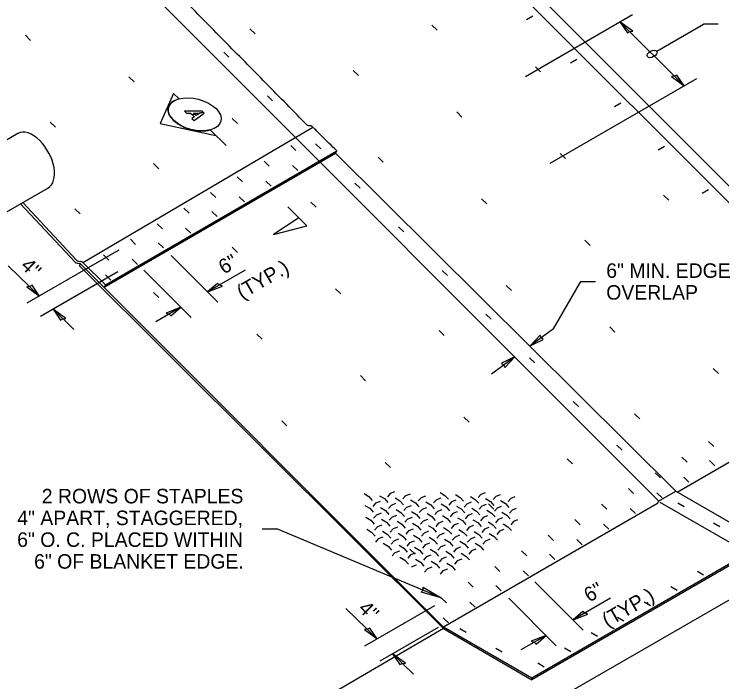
# Model space of a CAD drawing. Extents: x 99862 to 103151, y 100000 to 102076.
# Drawn here: x 101630 to 102411, y 100758 to 101495 of the extents above; entities that cross this region are included whole.
import ezdxf

# ---------------------------------------------------------------- set-up
doc = ezdxf.new("R2010")
doc.units = 0
for name, color, linetype in [('Level 1', 7, 'Continuous'), ('Level 11', 7, 'Continuous'), ('Level 15', 7, 'Continuous'), ('Level 20', 7, 'Continuous'), ('Level 3', 7, 'Continuous'), ('Level 36', 7, 'Continuous'), ('Level 4', 7, 'Continuous'), ('Level 5', 7, 'Continuous'), ('Level 7', 7, 'Continuous')]:
    doc.layers.add(name, color=color, linetype=linetype)

msp = doc.modelspace()

# ---------------------------------------------------------------- linework, layer by layer
at = {"layer": 'Level 1'}
for p, q in [((102612.56, 101110.84), (101833.9, 101890.08)), ((102742.49, 101035.83), (101698.37, 100433.01)), ((102103.79, 100817.24), (101571.09, 100506.49))]:
    msp.add_line(p, q, dxfattribs=at)
at = {"layer": 'Level 11'}
for points in [[(102016.17, 100965.97), (102021.52, 100962.7), (102025.25, 100958.36)], [(102033.32, 100963.67), (102038.66, 100960.4), (102042.39, 100956.07)], [(102049.88, 100967.79), (102044.98, 100965.91), (102041.87, 100962.52)], [(102066.87, 100965.49), (102062, 100963.62), (102058.92, 100960.22)], [(102083.8, 100963.2), (102078.95, 100961.33), (102075.91, 100957.94)], [(102100.05, 100967.3), (102105.33, 100964.06), (102109.06, 100959.78)], [(102116.82, 100965.02), (102122.09, 100961.79), (102125.82, 100957.52)], [(102133.52, 100962.74), (102138.78, 100959.52), (102142.51, 100955.26)], [(102149.49, 100966.81), (102144.78, 100964.96), (102141.85, 100961.61)], [(102166.04, 100964.55), (102161.36, 100962.7), (102158.46, 100959.35)], [(102182.52, 100962.29), (102177.87, 100960.45), (102175, 100957.1)], [(102033.82, 100957.21), (102028.88, 100955.32), (102025.73, 100951.89)], [(102050.93, 100954.93), (102046.02, 100953.03), (102042.9, 100949.6)], [(102050.41, 100961.37), (102055.73, 100958.11), (102059.46, 100953.78)], [(102067.42, 100959.08), (102072.74, 100955.82), (102076.47, 100951.51)], [(102084.37, 100956.8), (102089.68, 100953.55), (102093.41, 100949.24)], [(102100.65, 100960.92), (102095.84, 100959.05), (102092.82, 100955.66)], [(102101.26, 100954.53), (102106.55, 100951.28), (102110.29, 100946.98)], [(102117.45, 100958.65), (102112.66, 100956.78), (102109.67, 100953.39)], [(102134.17, 100956.39), (102129.42, 100954.51), (102126.46, 100951.13)], [(102150.84, 100954.13), (102146.11, 100952.26), (102143.18, 100948.88)], [(102150.16, 100960.48), (102155.41, 100957.27), (102159.14, 100953.01)], [(102166.74, 100958.23), (102171.98, 100955.02), (102175.71, 100950.77)], [(102017.12, 100953.03), (102022.49, 100949.75), (102026.22, 100945.39)], [(102034.33, 100950.74), (102039.68, 100947.46), (102043.42, 100943.11)], [(102051.46, 100948.46), (102056.8, 100945.19), (102060.55, 100940.85)], [(102067.98, 100952.64), (102063.09, 100950.75), (102060, 100947.32)], [(102068.53, 100946.19), (102073.86, 100942.92), (102077.61, 100938.59)], [(102084.95, 100950.37), (102080.09, 100948.48), (102077.04, 100945.06)], [(102101.86, 100948.11), (102097.03, 100946.21), (102094.01, 100942.8)], [(102118.07, 100952.26), (102123.36, 100949.03), (102127.1, 100944.73)], [(102134.83, 100950.01), (102140.1, 100946.78), (102143.84, 100942.49)], [(102151.51, 100947.76), (102156.78, 100944.54), (102160.52, 100940.26)], [(102167.43, 100951.89), (102162.74, 100950.02), (102159.83, 100946.64)], [(102183.97, 100949.65), (102179.3, 100947.78), (102176.42, 100944.41)], [(102018.08, 100940.01), (102023.46, 100936.71), (102027.21, 100932.33)], [(102034.83, 100944.25), (102029.87, 100942.33), (102026.72, 100938.87)], [(102051.99, 100941.98), (102047.06, 100940.06), (102043.94, 100936.6)], [(102069.08, 100939.72), (102064.18, 100937.8), (102061.09, 100934.35)], [(102085.53, 100943.93), (102090.85, 100940.67), (102094.6, 100936.34)], [(102102.46, 100941.67), (102107.78, 100938.42), (102111.53, 100934.1)], [(102118.7, 100945.86), (102113.91, 100943.96), (102110.91, 100940.55)], [(102119.33, 100939.43), (102124.64, 100936.18), (102128.39, 100931.87)], [(102135.48, 100943.61), (102130.71, 100941.72), (102127.74, 100938.31)], [(102152.19, 100941.37), (102147.45, 100939.48), (102144.51, 100936.08)], [(102168.84, 100939.15), (102164.13, 100937.25), (102161.22, 100933.85)], [(102168.14, 100945.53), (102173.39, 100942.31), (102177.14, 100938.04)], [(102035.84, 100931.2), (102030.86, 100929.26), (102027.7, 100925.77)], [(102035.33, 100937.74), (102040.7, 100934.45), (102044.46, 100930.07)], [(102052.52, 100935.47), (102057.88, 100932.19), (102061.64, 100927.83)], [(102069.64, 100933.22), (102074.99, 100929.94), (102078.75, 100925.59)], [(102086.11, 100937.46), (102081.24, 100935.54), (102078.18, 100932.1)], [(102086.7, 100930.98), (102092.04, 100927.71), (102095.79, 100923.35)], [(102103.07, 100935.22), (102098.23, 100933.3), (102095.2, 100929.86)], [(102119.97, 100932.98), (102115.16, 100931.07), (102112.15, 100927.63)], [(102136.79, 100930.75), (102132.01, 100928.84), (102129.04, 100925.4)], [(102136.14, 100937.19), (102141.43, 100933.95), (102145.18, 100929.64)], [(102152.87, 100934.96), (102158.16, 100931.73), (102161.91, 100927.43)], [(102169.55, 100932.75), (102174.82, 100929.52), (102178.58, 100925.22)], [(102185.42, 100936.93), (102180.74, 100935.04), (102177.86, 100931.64)], [(102019.04, 100926.9), (102024.44, 100923.59), (102028.2, 100919.19)], [(102036.35, 100924.65), (102041.74, 100921.34), (102045.5, 100916.95)], [(102053.06, 100928.95), (102048.11, 100927.01), (102044.98, 100923.52)], [(102070.2, 100926.7), (102065.29, 100924.76), (102062.19, 100921.28)], [(102087.28, 100924.47), (102082.4, 100922.53), (102079.32, 100919.05)], [(102103.68, 100928.74), (102109.01, 100925.48), (102112.77, 100921.13)], [(102120.6, 100926.51), (102125.92, 100923.26), (102129.69, 100918.92)], [(102137.45, 100924.3), (102142.77, 100921.04), (102146.53, 100916.71)], [(102153.56, 100928.54), (102148.81, 100926.62), (102145.86, 100923.19)], [(102170.25, 100926.33), (102165.53, 100924.41), (102162.61, 100920.98)], [(102036.86, 100918.07), (102031.87, 100916.1), (102028.7, 100912.59)], [(102054.13, 100915.83), (102049.17, 100913.87), (102046.03, 100910.36)], [(102053.59, 100922.4), (102058.97, 100919.11), (102062.73, 100914.72)], [(102070.76, 100920.17), (102076.13, 100916.88), (102079.9, 100912.5)], [(102087.87, 100917.94), (102093.22, 100914.66), (102097, 100910.29)], [(102104.29, 100922.24), (102099.44, 100920.3), (102096.4, 100916.83)], [(102104.91, 100915.72), (102110.25, 100912.45), (102114.03, 100908.08)], [(102121.24, 100920.02), (102116.41, 100918.09), (102113.4, 100914.62)], [(102138.12, 100917.82), (102133.32, 100915.88), (102130.34, 100912.41)], [(102154.93, 100915.62), (102150.17, 100913.68), (102147.21, 100910.22)], [(102154.24, 100922.09), (102159.54, 100918.84), (102163.31, 100914.52)], [(102037.37, 100911.47), (102042.77, 100908.16), (102046.55, 100903.74)], [(102054.66, 100909.25), (102060.06, 100905.94), (102063.84, 100901.53)], [(102071.33, 100913.61), (102066.4, 100911.65), (102063.29, 100908.14)], [(102071.89, 100907.03), (102077.27, 100903.73), (102081.06, 100899.33)], [(102088.46, 100911.39), (102083.56, 100909.43), (102080.48, 100905.93)], [(102105.52, 100909.19), (102100.65, 100907.22), (102097.6, 100903.72)], [(102121.88, 100913.52), (102127.21, 100910.25), (102130.99, 100905.89)], [(102138.78, 100911.32), (102144.11, 100908.05), (102147.89, 100903.7)], [(102055.2, 100902.64), (102050.23, 100900.65), (102047.15, 100897.19)], [(102072.46, 100900.43), (102067.51, 100898.44), (102064.39, 100894.91)], [(102089.05, 100904.82), (102094.42, 100901.53), (102098.21, 100897.14)], [(102106.14, 100902.63), (102111.5, 100899.34), (102115.29, 100894.95)], [(102122.52, 100906.99), (102117.68, 100905.03), (102114.66, 100901.53)], [(102123.16, 100900.44), (102128.52, 100897.16), (102132.3, 100892.78)], [(102139.45, 100904.8), (102134.64, 100902.84), (102131.65, 100899.34)], [(102055.75, 100896.01), (102061.16, 100892.69), (102064.95, 100888.26)], [(102073.03, 100893.81), (102078.43, 100890.5), (102082.22, 100886.08)], [(102089.64, 100898.23), (102084.73, 100896.25), (102081.64, 100892.71)], [(102090.24, 100891.62), (102095.63, 100888.32), (102099.43, 100883.9)], [(102106.76, 100896.04), (102101.87, 100894.06), (102098.82, 100890.53)], [(102123.81, 100893.86), (102118.95, 100891.88), (102115.92, 100888.36)], [(102073.6, 100887.17), (102068.64, 100885.16), (102068.32, 100884.8)], [(102090.83, 100884.99), (102085.9, 100882.98), (102082.81, 100879.42)], [(102107.38, 100889.44), (102112.76, 100886.14), (102116.56, 100881.74)], [(102108, 100882.82), (102103.1, 100880.81), (102100.04, 100877.25)]]:
    msp.add_lwpolyline(points, dxfattribs=at)
at = {"layer": 'Level 15'}
for p, q in [((102194.01, 101425.83), (102312.15, 101494.04)), ((102298.3, 101486.04), (102369.08, 101415.47)), ((102338.89, 101453.75), (102390.36, 101483.47)), ((102406.36, 101483.47), (102390.36, 101483.47)), ((102221.35, 101330.17), (102382.94, 101423.47)), ((101745.82, 101234.34), (101644.47, 101175.82)), ((101803.54, 101228.57), (101855.02, 101177.06)), ((101623.91, 101217.28), (101658.32, 101183.82)), ((101773.23, 101212.39), (101825.54, 101160.04)), ((101884.98, 101212.21), (101843.71, 101188.38)), ((101744.65, 101210.44), (101659.45, 101161.25)), ((102225.11, 101147.79), (102255.16, 101199.84)), ((102255.16, 101199.84), (102271.16, 101199.84)), ((101673.3, 101169.25), (101696.24, 101146.94)), ((101814.23, 101171.36), (101786.52, 101155.36)), ((102225.11, 101147.79), (102199.26, 101128.94)), ((102182.33, 101116.59), (102156.47, 101097.74)), ((101903.92, 100927.21), (101919.92, 100927.21)), ((102101.29, 100851.14), (101919.92, 100927.21)), ((102204.42, 100868.85), (102257.83, 100815.41)), ((102175.79, 100850.59), (102228.1, 100798.24)), ((102287.79, 100850.55), (102246.52, 100826.72)), ((101996.16, 100839.29), (102030.57, 100805.83)), ((102093.76, 100842.31), (102016.72, 100797.83)), ((102097.77, 100818.33), (102033.69, 100781.33)), ((102216.79, 100809.56), (102189.08, 100793.56)), ((102047.54, 100789.33), (102070.48, 100767.02))]:
    msp.add_line(p, q, dxfattribs=at)
for points in [[(102298.3, 101486.04), (102306.46, 101474.13), (102308.92, 101475.45), (102312.41, 101475.74)], [(102369.08, 101415.47), (102360.92, 101427.37), (102358.46, 101426.06), (102354.97, 101425.77)], [(101658.32, 101183.82), (101650.16, 101195.72), (101647.7, 101194.41), (101644.21, 101194.12)], [(101843.71, 101188.38), (101860, 101194.7), (101856.7, 101195.88), (101854.66, 101197.79)], [(101673.3, 101169.25), (101681.46, 101157.34), (101683.93, 101158.66), (101687.42, 101158.94)], [(101814.23, 101171.36), (101797.94, 101165.04), (101801.24, 101163.86), (101803.28, 101161.95)], [(102199.26, 101128.94), (102213.78, 101135.71), (102211.37, 101137.77), (102210.14, 101140.69)], [(102182.33, 101116.59), (102167.8, 101109.82), (102170.21, 101107.76), (102171.44, 101104.84)], [(102101.29, 100851.14), (102079.08, 100857.22), (102081.21, 100859.56), (102081.39, 100862.72)], [(102246.52, 100826.72), (102262.81, 100833.05), (102259.51, 100834.22), (102257.47, 100836.13)], [(102030.57, 100805.83), (102022.41, 100817.74), (102019.95, 100816.42), (102016.46, 100816.13)], [(102216.79, 100809.56), (102200.5, 100803.24), (102203.8, 100802.06), (102205.84, 100800.15)], [(102047.54, 100789.33), (102055.7, 100777.42), (102058.17, 100778.74), (102061.66, 100779.02)]]:
    msp.add_lwpolyline(points, close=True, dxfattribs=at)
msp.add_ellipse((102333.69, 101450.75), major_axis=(-5.2, -3), ratio=0.57735, dxfattribs=at)
at = {"layer": 'Level 20'}
for p, q in [((101806.09, 101407.27), (101791.22, 101374.02)), ((101806.09, 101407.27), (101791.22, 101374.02)), ((101812.18, 101401.22), (101806.09, 101407.27)), ((101812.18, 101401.22), (101806.09, 101407.27)), ((101829.66, 101384.17), (101826.99, 101383.46)), ((101826.99, 101383.46), (101829.66, 101384.17)), ((101834.97, 101385.59), (101835, 101385.6)), ((101838.85, 101386.63), (101835, 101385.6)), ((101835, 101385.6), (101838.85, 101386.63)), ((101791.22, 101374.02), (101852.74, 101360.96)), ((101791.22, 101374.02), (101852.74, 101360.96)), ((101846.65, 101367.01), (101863.96, 101349.82)), ((101852.74, 101360.96), (101846.65, 101367.01)), ((101852.74, 101360.96), (101846.65, 101367.01)), ((101932.03, 101282.24), (101953.11, 101261.31))]:
    msp.add_line(p, q, dxfattribs=at)
for points in [[(101829.08, 101381.38), (101826.44, 101379.52), (101828.72, 101377.26), (101839.9, 101385.59), (101837.8, 101387.68), (101818.1, 101387.8), (101820.4, 101385.51), (101824.9, 101385.54), (101829.08, 101381.38)], [(101838.85, 101386.63), (101837.8, 101387.68), (101818.1, 101387.8), (101820.4, 101385.51), (101824.9, 101385.54), (101826.99, 101383.46)], [(101826.99, 101383.46), (101829.08, 101381.38), (101826.44, 101379.52), (101828.72, 101377.26), (101839.9, 101385.59), (101838.85, 101386.63)], [(101835, 101385.59), (101831.05, 101382.79), (101828.27, 101385.55), (101835, 101385.59)], [(101829.66, 101384.17), (101828.27, 101385.55), (101834.97, 101385.59)], [(101835, 101385.59), (101831.05, 101382.79), (101829.66, 101384.17)], [(101835, 101385.6), (101835, 101385.59)], [(101944.19, 101270.16), (101916.16, 101251.54), (101953.11, 101261.31), (101944.19, 101270.16)]]:
    msp.add_lwpolyline(points, dxfattribs=at)
msp.add_ellipse((101829.41, 101384.11), major_axis=(28.93, -7.57), ratio=0.572616, dxfattribs=at)
for start_param, end_param in [(2.349236, 5.49092), (2.349236, 3.025373), (3.025373, 3.920085), (3.920085, 5.49092)]:
    msp.add_ellipse((101829.41, 101384.11), major_axis=(28.93, -7.57), ratio=0.572616, start_param=start_param, end_param=end_param, dxfattribs=at)
at = {"layer": 'Level 3'}
for p, q in [((101634.49, 101362.93), (101379.93, 101215.96)), ((101413.08, 101155.93), (101667.64, 101302.9)), ((101413.08, 101155.93), (101667.64, 101302.9))]:
    msp.add_line(p, q, dxfattribs=at)
for centre, major_axis, start_param, end_param in [((101650.74, 101334.78), (-16.25, 28.15), 5.148721, 6.283185), ((101650.14, 101333.21), (-17.5, 30.31), 3.141593, 5.148721)]:
    msp.add_ellipse(centre, major_axis=major_axis, ratio=0.57735, start_param=start_param, end_param=end_param, dxfattribs=at)
at = {"layer": 'Level 36'}
for p, q in [((102202.37, 101492.39), (102195.36, 101488.37)), ((101890.22, 101478.43), (101896.01, 101472.8)), ((102090.94, 101482.46), (102096.73, 101476.83)), ((101642.72, 101471.26), (101648.51, 101465.63)), ((101861.44, 101452.63), (101867.22, 101447)), ((102250.74, 101444.49), (102243.73, 101440.47)), ((102004.25, 101432.62), (102010.04, 101426.99)), ((102204.97, 101436.64), (102210.76, 101431.02)), ((101756.75, 101425.44), (101762.54, 101419.81)), ((101909.59, 101404.5), (101915.37, 101398.87)), ((102299.11, 101396.58), (102292.11, 101392.57)), ((102118.28, 101386.8), (102124.07, 101381.17)), ((101670.06, 101375.6), (101675.84, 101369.97)), ((101870.78, 101379.63), (101876.57, 101374)), ((101935.3, 101349.71), (101941.09, 101344.08)), ((101962.72, 101351.75), (101968.51, 101346.12)), ((102347.48, 101348.68), (102340.48, 101344.66)), ((102031.59, 101336.96), (102037.38, 101331.33)), ((102232.31, 101340.99), (102238.1, 101335.36)), ((101784.09, 101329.79), (101789.87, 101324.16)), ((101905.84, 101332.49), (101911.63, 101326.86)), ((101937.33, 101327.66), (101943.11, 101322.03)), ((101876.37, 101315.26), (101882.16, 101309.63)), ((101907.86, 101310.44), (101913.65, 101304.81)), ((102005.89, 101308.26), (102011.68, 101302.63)), ((101846.9, 101298.04), (101852.69, 101292.41)), ((102395.85, 101300.78), (102388.85, 101296.76)), ((101878.39, 101293.21), (101884.18, 101287.58)), ((102145.62, 101291.14), (102151.41, 101285.51)), ((102346.34, 101295.17), (102352.13, 101289.54)), ((101957.4, 101287.41), (101963.19, 101281.78)), ((101697.39, 101279.94), (101703.18, 101274.31)), ((101817.44, 101280.81), (101823.22, 101275.18)), ((101848.29, 101277.04), (101854.08, 101271.41)), ((101787.97, 101263.58), (101793.76, 101257.95)), ((101819.46, 101258.76), (101825.25, 101253.13)), ((102054.04, 101260.13), (102059.83, 101254.5)), ((101758.5, 101246.35), (101764.29, 101240.72)), ((101789.15, 101242.57), (101794.94, 101236.94)), ((102259.65, 101245.33), (102265.44, 101239.7)), ((101870.71, 101237.56), (101876.49, 101231.93)), ((101729.04, 101229.13), (101734.82, 101223.5)), ((101760.52, 101224.3), (101766.31, 101218.67)), ((102102.19, 101212.01), (102107.98, 101206.38)), ((101731.06, 101207.08), (101736.85, 101201.45)), ((101984.74, 101191.75), (101990.52, 101186.12)), ((102172.95, 101195.48), (102178.74, 101189.85)), ((101784.01, 101187.72), (101789.8, 101182.09)), ((102150.34, 101163.88), (102156.13, 101158.25)), ((102286.99, 101149.67), (102292.77, 101144.04)), ((101898.04, 101141.9), (101903.83, 101136.27)), ((102098.77, 101145.93), (102104.56, 101140.3)), ((102198.49, 101115.76), (102204.28, 101110.13)), ((102401.02, 101103.85), (102406.8, 101098.22)), ((102012.07, 101096.09), (102017.86, 101090.46)), ((102246.64, 101067.64), (102252.43, 101062.01)), ((102126.1, 101050.27), (102131.89, 101044.64)), ((102314.32, 101054.01), (102320.11, 101048.38)), ((101925.38, 101046.24), (101931.17, 101040.61)), ((102294.79, 101019.51), (102300.58, 101013.88)), ((102395.95, 101023.41), (102401.74, 101017.78)), ((102240.14, 101004.46), (102245.92, 100998.83)), ((102366.49, 101006.18), (102372.28, 101000.55)), ((102397.14, 101002.4), (102402.92, 100996.77)), ((102039.41, 101000.43), (102045.2, 100994.8)), ((102337.02, 100988.95), (102342.81, 100983.32)), ((102368.51, 100984.13), (102374.3, 100978.5)), ((102307.55, 100971.73), (102313.34, 100966.1)), ((102339.04, 100966.9), (102344.83, 100961.27)), ((102153.44, 100954.61), (102159.23, 100948.98)), ((102278.09, 100954.5), (102283.88, 100948.87)), ((102362.16, 100955.97), (102369.11, 100951.87)), ((102309.58, 100949.68), (102315.37, 100944.05)), ((102248.62, 100937.27), (102254.41, 100931.64)), ((102280.11, 100932.45), (102285.9, 100926.82)), ((102401.38, 100933.69), (102408.33, 100929.59)), ((102219.15, 100920.05), (102224.94, 100914.42)), ((102250.64, 100915.22), (102256.43, 100909.59)), ((102066.75, 100904.77), (102072.54, 100899.14)), ((102189.69, 100902.82), (102195.48, 100897.19)), ((102220.54, 100899.06), (102226.33, 100893.43)), ((102160.22, 100885.6), (102166.01, 100879.97)), ((102191.71, 100880.77), (102197.5, 100875.14)), ((102383.58, 100880.54), (102390.53, 100876.44)), ((102130.75, 100868.37), (102136.54, 100862.74)), ((102161.4, 100864.58), (102167.19, 100858.95)), ((102354.29, 100863.65), (102361.25, 100859.55)), ((102101.29, 100851.14), (102107.08, 100845.51)), ((102132.78, 100846.32), (102138.56, 100840.69)), ((102325, 100846.77), (102331.96, 100842.67)), ((102103.31, 100829.09), (102109.1, 100823.46)), ((102295.72, 100829.88), (102302.67, 100825.78)), ((102121.85, 100817.3), (102128.8, 100813.2)), ((102266.43, 100813), (102273.39, 100808.9)), ((102161.42, 100795.7), (102168.37, 100791.6)), ((102237.14, 100796.11), (102244.1, 100792.01)), ((102207.86, 100779.23), (102214.81, 100775.13))]:
    msp.add_line(p, q, dxfattribs=at)
at = {"layer": 'Level 4'}
for p, q in [((101729.52, 101193.46), (101984.5, 101341.14)), ((101731.12, 101196.16), (101986.09, 101343.82)), ((101984.5, 101341.14), (101986.09, 101343.82)), ((101637.26, 101285.36), (101697.46, 101221.09)), ((101699.22, 101223.31), (101640.04, 101286.97)), ((101699.91, 101219.93), (101702.23, 101219.7)), ((101701.4, 101222.17), (101703.87, 101221.75)), ((101731.12, 101196.16), (101706.02, 101220.64)), ((101702.49, 101217.14), (102103.79, 100817.24)), ((102103.79, 100818.86), (101704.4, 101218.59)), ((101731.12, 101196.16), (101729.52, 101193.46)), ((102359.74, 100968.49), (102457.18, 100912.24)), ((102340.16, 100956.47), (102340.16, 100956.06)), ((102201.23, 100762.61), (102103.79, 100818.86)), ((102103.79, 100818.86), (102103.79, 100817.24)), ((102103.79, 100817.24), (102201.23, 100760.76)), ((102201.23, 100760.76), (102201.23, 100762.61))]:
    msp.add_line(p, q, dxfattribs=at)
for points in [[(102359.74, 100968.49), (101984.5, 101341.14)], [(101702.49, 101217.14), (101703.58, 101219.22)], [(102340.79, 100957.55), (102359.74, 100968.49)], [(102339.54, 100954.98), (102103.79, 100818.86)], [(102436.98, 100898.72), (102201.23, 100762.61)], [(102438.45, 100897.71), (102201.23, 100760.76)]]:
    msp.add_lwpolyline(points, dxfattribs=at)
for centre, radius, start, end in [((101700.29, 101223.91), 4, 224.83911, 264.43475), ((101702.07, 101226.12), 4, 224.56642, 260.35108), ((101701.59, 101215.76), 3.99, 45.09638, 80.63404), ((101703.2, 101217.81), 4, 45.09263, 80.35108), ((102338.91, 100956.06), 1.25, 300, 0), ((102341.41, 100956.47), 1.25, 120, 180)]:
    msp.add_arc(centre, radius, start, end, dxfattribs=at)
for points, degree in [([(101953.72, 101371.89), (101768.44, 101560.71), (101576.5, 101752.84)], 2), ([(101986.09, 101343.82), (101969.95, 101359.77), (101959.61, 101370.08), (101958.24, 101371.44), (101956.92, 101371.5), (101955.71, 101371.56), (101954.51, 101371.62), (101954.13, 101371.63), (101953.72, 101371.89)], 4)]:
    msp.add_open_spline(points, degree=degree, dxfattribs=at)
at = {"layer": 'Level 5'}
for p, q in [((102599.7, 101105.18), (101816.91, 101888.55)), ((102361.35, 100967.57), (102599.7, 101105.18))]:
    msp.add_line(p, q, dxfattribs=at)
at = {"layer": 'Level 7'}
for p, q in [((102341.08, 100957.72), (101557.51, 101741.88)), ((101706.81, 101220.97), (101959.63, 101370.06)), ((102342.25, 100956.55), (102439.7, 100900.29))]:
    msp.add_line(p, q, dxfattribs=at)

# ---------------------------------------------------------------- texts
at = {"layer": 'Level 20'}
for s, rotation, p in [('6" ', 29.99868, (101861.6, 101207.35)), ('4"', 315.43196, (101636.56, 101216.05)), ('(TYP.)', 29.99868, (101881.58, 101179.75)), ('6" ', 29.99868, (102264.42, 100845.7)), ('(TYP.)', 29.99868, (102284.39, 100818.1)), ('4"', 315.43196, (102008.82, 100838.07))]:
    msp.add_text(s, height=16, rotation=rotation, dxfattribs=at).set_placement(p)
for s, p in [('6" MIN. EDGE', (102283.17, 101203.84)), ('OVERLAP', (102283.17, 101179.84)), ('2 ROWS OF STAPLES', (101660.79, 100955.21)), ('4" APART, STAGGERED,', (101633.77, 100931.21)), ('6" O. C. PLACED WITHIN', (101633.68, 100907.21)), ('6" OF BLANKET EDGE.', (101652.37, 100883.21))]:
    msp.add_text(s, height=16, dxfattribs=at).set_placement(p)

doc.saveas('drawing.dxf')
